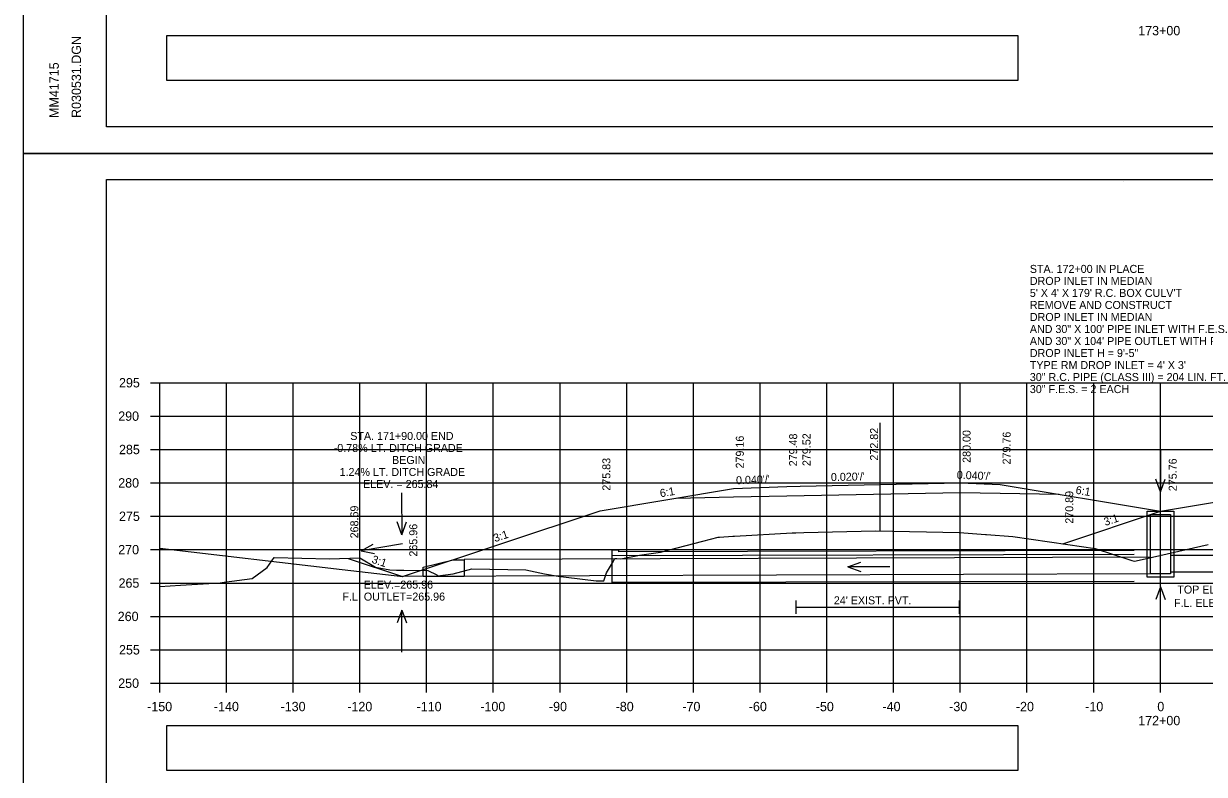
# Model space of a CAD drawing. Extents: x 285 to 4233, y -659 to 3710.
# Drawn here: x 1053.3 to 1230.3, y 1572.6 to 1685 of the extents above; entities that cross this region are included whole.
import ezdxf

# ---------------------------------------------------------------- set-up
doc = ezdxf.new("R2010")
doc.units = 0
for name, color, linetype in [('R_Alt Surface', 7, 'Continuous'), ('R_Axis', 7, 'Continuous'), ('R_Axis Annot', 7, 'Continuous'), ('R_Border', 7, 'Continuous'), ('R_Exist Surface', 7, 'Continuous'), ('R_Fin Surface', 7, 'Continuous'), ('R_Grid', 7, 'Continuous'), ('R_No Plot', 7, 'Continuous'), ('R_Water', 7, 'Continuous'), ('R_Water Annot', 7, 'Continuous'), ('R_Xsect Elev', 7, 'Continuous'), ('R_Xsect Slope', 7, 'Continuous')]:
    doc.layers.add(name, color=color, linetype=linetype)

# ---------------------------------------------------------------- blocks, each defined once
blk = doc.blocks.new('FES30LT_P')
at = {"layer": 'R_Water'}
blk.add_lwpolyline([(1.646, 0), (1.646, -2.5), (-4.5, -2.5), (-4.5, -1.115), (0, 0)], close=True, dxfattribs=at)

msp = doc.modelspace()

# ---------------------------------------------------------------- linework, layer by layer
at = {"layer": 'R_Alt Surface'}
for points in [[(1151.11, 1613.97), (1159.68, 1614.14), (1167.68, 1614.3), (1193.68, 1614.82), (1193.68, 1614.82), (1199.68, 1614.7), (1208.52, 1614.53)], [(1169.03, 1598.61), (1169.03, 1596.61)], [(1193.52, 1598.61), (1193.52, 1596.61)], [(1169.03, 1597.61), (1193.52, 1597.61)]]:
    msp.add_lwpolyline(points, dxfattribs=at)
at = {"layer": 'R_Axis'}
for p, q in [((1072.28, 1631.24), (1073.68, 1631.24)), ((1073.68, 1586.24), (1073.68, 1631.24)), ((1072.28, 1626.24), (1073.68, 1626.24)), ((1072.28, 1621.24), (1073.68, 1621.24)), ((1072.28, 1616.24), (1073.68, 1616.24)), ((1072.28, 1611.24), (1073.68, 1611.24)), ((1072.28, 1606.24), (1073.68, 1606.24)), ((1072.28, 1601.24), (1073.68, 1601.24)), ((1072.28, 1596.24), (1073.68, 1596.24)), ((1072.28, 1591.24), (1073.68, 1591.24)), ((1072.28, 1586.24), (1073.68, 1586.24)), ((1073.68, 1586.24), (1373.68, 1586.24)), ((1073.68, 1584.84), (1073.68, 1586.24)), ((1083.68, 1584.84), (1083.68, 1586.24)), ((1093.68, 1584.84), (1093.68, 1586.24)), ((1103.68, 1584.84), (1103.68, 1586.24)), ((1113.68, 1584.84), (1113.68, 1586.24)), ((1123.68, 1584.84), (1123.68, 1586.24)), ((1133.68, 1584.84), (1133.68, 1586.24)), ((1143.68, 1584.84), (1143.68, 1586.24)), ((1153.68, 1584.84), (1153.68, 1586.24)), ((1163.68, 1584.84), (1163.68, 1586.24)), ((1173.68, 1584.84), (1173.68, 1586.24)), ((1183.68, 1584.84), (1183.68, 1586.24)), ((1193.68, 1584.84), (1193.68, 1586.24)), ((1203.68, 1584.84), (1203.68, 1586.24)), ((1213.68, 1584.84), (1213.68, 1586.24)), ((1223.68, 1584.84), (1223.68, 1586.24))]:
    msp.add_line(p, q, dxfattribs=at)
at = {"layer": 'R_Axis Annot'}
for points in [[(1074.67, 1676.54), (1202.36, 1676.54), (1202.36, 1683.2), (1074.67, 1683.2)], [(1074.67, 1573.2), (1202.36, 1573.2), (1202.36, 1579.86), (1074.67, 1579.86)]]:
    msp.add_lwpolyline(points, close=True, dxfattribs=at)
at = {"layer": 'R_Border'}
for p, q in [((1065.68, 1669.58), (1065.68, 1875.04)), ((1065.68, 1669.58), (1065.68, 1669.58)), ((1381.86, 1669.58), (1065.68, 1669.58)), ((1065.68, 1661.7), (1381.86, 1661.7)), ((1065.68, 1456.24), (1065.68, 1661.7)), ((1218.2, 1661.44), (1218.2, 1661.44)), ((1218.2, 1661.44), (1218.2, 1661.44))]:
    msp.add_line(p, q, dxfattribs=at)
at = {"layer": 'R_Exist Surface'}
msp.add_lwpolyline([(1073.68, 1600.74), (1076.78, 1600.9), (1082.72, 1601.27), (1083.31, 1601.36), (1087.53, 1601.9), (1089.77, 1603.56), (1090.83, 1605.05), (1099.14, 1604.84), (1103.67, 1604.99), (1106, 1603.61), (1108.15, 1603.24), (1109.18, 1603.17), (1109.2, 1603.15), (1110.29, 1603.16), (1113.88, 1603.12), (1115.23, 1602.46), (1115.32, 1602.35), (1115.34, 1602.34), (1117.66, 1602.63), (1120.44, 1603.38), (1128.56, 1603.21), (1131.36, 1602.64), (1133.38, 1602.29), (1134.59, 1602.1), (1139.1, 1601.57), (1140.26, 1601.56), (1140.65, 1602.76), (1141.53, 1604.25), (1141.9, 1604.9), (1142.19, 1604.92), (1142.79, 1604.86), (1145.61, 1605.39), (1148.73, 1605.88), (1155.1, 1607.51), (1157.38, 1608.11), (1157.58, 1608.1), (1159.6, 1608.25), (1159.82, 1608.27), (1168.49, 1608.75), (1169.03, 1608.78), (1170.22, 1608.81), (1180.98, 1609.08), (1188.62, 1608.92), (1193.52, 1608.82), (1193.56, 1608.82), (1197.48, 1608.52), (1197.6, 1608.51), (1201.56, 1608.22), (1209.79, 1607.02), (1213.91, 1606.41), (1219.41, 1604.63), (1219.78, 1604.53), (1221.38, 1604.86), (1230.82, 1607)], dxfattribs=at)
at = {"layer": 'R_Fin Surface'}
for points in [[(1101.9, 1604.93), (1110.09, 1602.2), (1139.68, 1612.07), (1159.68, 1615.4), (1167.68, 1615.72), (1169.68, 1615.76), (1193.68, 1616.24), (1199.68, 1616), (1223.68, 1612)], [(1209.07, 1607.13), (1223.68, 1612), (1247.68, 1616), (1253.68, 1616.24), (1277.68, 1615.76), (1279.68, 1615.72), (1287.68, 1615.4), (1307.68, 1612.07), (1334.16, 1603.24), (1342.83, 1606.13)], [(1073.68, 1606.47), (1101.02, 1603.27), (1110.1, 1602.21)]]:
    msp.add_lwpolyline(points, dxfattribs=at)
at = {"layer": 'R_Grid'}
for p, q in [((1073.68, 1631.24), (1373.68, 1631.24)), ((1073.68, 1586.24), (1073.68, 1631.24)), ((1083.68, 1586.24), (1083.68, 1631.24)), ((1093.68, 1586.24), (1093.68, 1631.24)), ((1103.68, 1586.24), (1103.68, 1631.24)), ((1113.68, 1586.24), (1113.68, 1631.24)), ((1123.68, 1586.24), (1123.68, 1631.24)), ((1133.68, 1586.24), (1133.68, 1631.24)), ((1143.68, 1586.24), (1143.68, 1631.24)), ((1153.68, 1586.24), (1153.68, 1631.24)), ((1163.68, 1586.24), (1163.68, 1631.24)), ((1173.68, 1586.24), (1173.68, 1631.24)), ((1183.68, 1586.24), (1183.68, 1631.24)), ((1193.68, 1586.24), (1193.68, 1631.24)), ((1203.68, 1586.24), (1203.68, 1631.24)), ((1213.68, 1586.24), (1213.68, 1631.24)), ((1223.68, 1586.24), (1223.68, 1631.24)), ((1073.68, 1626.24), (1373.68, 1626.24)), ((1073.68, 1621.24), (1373.68, 1621.24)), ((1073.68, 1616.24), (1373.68, 1616.24)), ((1073.68, 1611.24), (1373.68, 1611.24)), ((1073.68, 1606.24), (1373.68, 1606.24)), ((1073.68, 1601.24), (1373.68, 1601.24)), ((1073.68, 1596.24), (1373.68, 1596.24)), ((1073.68, 1591.24), (1373.68, 1591.24)), ((1073.68, 1586.24), (1373.68, 1586.24))]:
    msp.add_line(p, q, dxfattribs=at)
at = {"layer": 'R_No Plot'}
for p, q in [((1053.28, 1665.6), (1386.61, 1665.6)), ((1053.28, 1665.59), (1386.61, 1665.59))]:
    msp.add_line(p, q, dxfattribs=at)
for points in [[(1053.27, 1878.93), (1386.61, 1878.93), (1386.61, 1665.59), (1053.27, 1665.59)], [(1299.6, 1875.04), (1319.22, 1875.04), (1319.22, 1865.16), (1335.33, 1865.16), (1358.53, 1865.16), (1358.65, 1837), (1381.86, 1837), (1381.86, 1669.58), (1065.68, 1669.58), (1065.68, 1875.04)], [(1053.27, 1665.59), (1386.61, 1665.59), (1386.61, 1452.26), (1053.27, 1452.26)], [(1299.6, 1661.7), (1319.22, 1661.7), (1319.22, 1651.82), (1335.33, 1651.82), (1358.53, 1651.82), (1358.65, 1623.66), (1381.86, 1623.66), (1381.86, 1456.24), (1065.68, 1456.24), (1065.68, 1661.7)]]:
    msp.add_lwpolyline(points, close=True, dxfattribs=at)
at = {"layer": 'R_Water'}
for p, q in [((1142.43, 1606.18), (1141.43, 1606.17)), ((1141.43, 1606.17), (1141.43, 1601.14)), ((1219.77, 1605.49), (1141.44, 1605.3)), ((1142.43, 1606.18), (1142.43, 1605.93)), ((1219.77, 1606.11), (1142.43, 1605.93)), ((1325.09, 1605.71), (1225.18, 1605.35)), ((1222.18, 1605.1), (1119.31, 1604.74)), ((1222.18, 1602.6), (1110.09, 1602.2)), ((1334.16, 1603.24), (1225.18, 1602.85)), ((1219.77, 1601.49), (1141.44, 1601.3))]:
    msp.add_line(p, q, dxfattribs=at)
for points in [[(1223.68, 1612), (1225.68, 1612), (1225.68, 1602.1), (1223.68, 1602.1), (1221.68, 1602.1), (1221.68, 1612)], [(1223.68, 1611.5), (1225.18, 1611.5), (1225.18, 1602.6), (1223.68, 1602.6), (1222.18, 1602.6), (1222.18, 1611.5)]]:
    msp.add_lwpolyline(points, close=True, dxfattribs=at)
at = {"layer": 'R_Water Annot'}
for p, q in [((1223.68, 1621.16), (1223.68, 1614.88)), ((1223.68, 1614.88), (1222.98, 1616.8)), ((1223.68, 1614.88), (1224.38, 1616.8)), ((1109.94, 1614.75), (1109.96, 1608.47)), ((1109.96, 1608.47), (1109.25, 1610.39)), ((1109.96, 1608.47), (1110.65, 1610.39)), ((1110.06, 1607.11), (1103.87, 1606.04)), ((1103.87, 1606.04), (1105.65, 1607.06)), ((1103.87, 1606.04), (1105.88, 1605.68)), ((1176.83, 1603.65), (1178.76, 1604.35)), ((1183.12, 1603.65), (1176.83, 1603.65)), ((1176.83, 1603.65), (1178.76, 1602.95)), ((1223.68, 1600.68), (1222.98, 1598.76)), ((1223.68, 1594.39), (1223.68, 1600.68)), ((1223.68, 1600.68), (1224.38, 1598.76)), ((1109.99, 1597.19), (1109.29, 1595.27)), ((1109.99, 1590.91), (1109.99, 1597.19)), ((1109.99, 1597.19), (1110.69, 1595.27))]:
    msp.add_line(p, q, dxfattribs=at)
at = {"layer": 'R_Xsect Elev'}
msp.add_line((1181.68, 1609.06), (1181.68, 1625.26), dxfattribs=at)

# ---------------------------------------------------------------- block references
at = {"layer": 'R_Water', "rotation": 0.20299054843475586}
msp.add_blockref('FES30LT_P', (1117.67, 1604.73), dxfattribs=at)

# ---------------------------------------------------------------- texts
at = {"layer": 'R_Axis Annot'}
for s, p in [('173+00', (1220.36, 1683.28)), ('295', (1067.57, 1630.54)), ('290', (1067.45, 1625.54)), ('285', (1067.57, 1620.54)), ('280', (1067.45, 1615.54)), ('275', (1067.57, 1610.54)), ('270', (1067.45, 1605.54)), ('265', (1067.5, 1600.54)), ('260', (1067.38, 1595.54)), ('255', (1067.57, 1590.54)), ('250', (1067.45, 1585.54)), ('-150', (1071.79, 1582.04)), ('-140', (1081.79, 1582.04)), ('-130', (1091.79, 1582.04)), ('-120', (1101.79, 1582.04)), ('-110', (1112.18, 1582.04)), ('-100', (1121.73, 1582.04)), ('-90', (1132.02, 1582.04)), ('-80', (1142.02, 1582.04)), ('-70', (1152.02, 1582.04)), ('-60', (1161.98, 1582.04)), ('-50', (1172.02, 1582.04)), ('-40', (1182.02, 1582.04)), ('-30', (1192.02, 1582.04)), ('-20', (1202.02, 1582.04)), ('-10', (1212.41, 1582.04)), ('0', (1223.22, 1582.04)), ('172+00', (1220.36, 1579.94))]:
    msp.add_text(s, height=1.4, dxfattribs=at).set_placement(p)
at = {"layer": 'R_Border'}
for s, p in [('R030531.DGN', (1061.87, 1670.9)), ('MM41715', (1058.54, 1670.9))]:
    msp.add_text(s, height=1.4, rotation=90, dxfattribs=at).set_placement(p)
at = {"layer": 'R_Water'}
msp.add_text("24' EXIST. PVT.", height=1.2, dxfattribs=at).set_placement((1174.73, 1598.05))
at = {"layer": 'R_Water Annot'}
for s, p in [('STA. 172+00 IN PLACE', (1204.11, 1647.69)), ('DROP INLET IN MEDIAN', (1204.11, 1645.89)), ("5' X 4' X 179' R.C. BOX CULV'T ", (1204.11, 1644.09)), ('REMOVE AND CONSTRUCT', (1204.11, 1642.29)), ('DROP INLET IN MEDIAN', (1204.11, 1640.49)), ('AND 30" X 100\' PIPE INLET WITH F.E.S.', (1204.11, 1638.69)), ('AND 30" X 104\' PIPE OUTLET WITH F.E.S.', (1204.11, 1636.89)), ('DROP INLET H = 9\'-5"', (1204.11, 1635.09)), ("TYPE RM DROP INLET = 4' X 3'", (1204.11, 1633.29)), ('30" R.C. PIPE (CLASS III) = 204 LIN. FT.', (1204.11, 1631.49)), ('30" F.E.S. = 2 EACH', (1204.11, 1629.69)), ('TOP ELEV.= 275.76', (1226.22, 1599.66)), ('F.L. OUTLET=265.96', (1101.06, 1598.61)), ('F.L. ELEV.= 266.36', (1225.72, 1597.66))]:
    msp.add_text(s, height=1.2, dxfattribs=at).set_placement(p)
at = {"layer": 'R_Xsect Elev'}
for s, p in [('STA. 171+90.00 END', (1102.24, 1622.67)), ('-0.78% LT. DITCH GRADE', (1099.76, 1620.87)), ('BEGIN', (1108.5, 1619.07)), ('1.24% LT. DITCH GRADE', (1100.64, 1617.27)), ('ELEV. = 265.84', (1104.16, 1615.47)), ('ELEV.=265.96', (1104.25, 1600.4))]:
    msp.add_text(s, height=1.2, dxfattribs=at).set_placement(p)
for s, p in [('279.16', (1161.23, 1618.4)), ('279.48', (1169.23, 1618.72)), ('279.52', (1171.23, 1618.76)), ('272.82', (1181.36, 1619.58)), ('280.00', (1195.23, 1619.24)), ('279.76', (1201.23, 1619)), ('275.83', (1141.23, 1615.07)), ('275.76', (1226.13, 1615)), ('270.89', (1210.62, 1610.13)), ('268.69', (1103.45, 1607.93)), ('265.96', (1112.28, 1605.2))]:
    msp.add_text(s, height=1.2, rotation=90, dxfattribs=at).set_placement(p)
at = {"layer": 'R_Xsect Slope'}
for s, rotation, p in [("0.020'/'", 1.1458, (1174.3, 1616.51)), ("0.040'/'", 357.7094, (1193.14, 1616.86)), ("0.040'/'", 2.2907, (1160.09, 1616.02)), ('6:1', 9.4614, (1148.75, 1614.08)), ('6:1', 350.5375, (1210.91, 1614.63)), ('3:1', 18.4339, (1215.42, 1609.78)), ('3:1', 18.4358, (1123.93, 1607.35)), ('3:1', 341.5687, (1105.36, 1604.3))]:
    msp.add_text(s, height=1.2, rotation=rotation, dxfattribs=at).set_placement(p)

doc.saveas('drawing.dxf')
